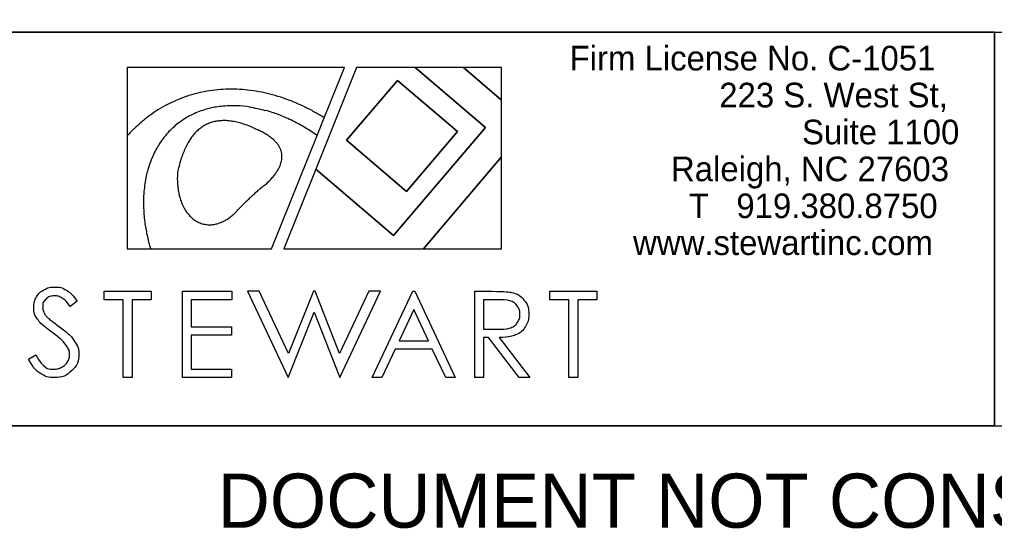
# Model space of a CAD drawing. Extents: x 1637092 to 1638792, y 884647 to 885778.
# Drawn here: x 1638567.6 to 1638666.6, y 885534.2 to 885585.9 of the extents above; entities that cross this region are included whole.
import ezdxf

# ---------------------------------------------------------------- set-up
doc = ezdxf.new("R2010")
doc.units = 0
for name, color, linetype in [('Default', 7, 'Continuous'), ('Sheet Plan And Profile CELL', 7, 'Continuous'), ('Sheet Profile CELL', 7, 'Continuous')]:
    doc.layers.add(name, color=color, linetype=linetype)

msp = doc.modelspace()

# ---------------------------------------------------------------- linework, layer by layer
at = {"layer": 'Default'}
for p, q in [((1638600.578, 885580.988), (1638578.504, 885580.988)), ((1638578.504, 885580.988), (1638578.504, 885574.036)), ((1638601.809, 885580.988), (1638597.661, 885570.674)), ((1638598.525, 885575.881), (1638600.578, 885580.988)), ((1638607.761, 885580.988), (1638601.809, 885580.988)), ((1638607.761, 885580.988), (1638614.913, 885574.896)), ((1638612.655, 885580.988), (1638607.761, 885580.988)), ((1638614.913, 885574.896), (1638607.761, 885580.988)), ((1638616.541, 885580.988), (1638612.655, 885580.988)), ((1638612.655, 885580.988), (1638616.541, 885577.678)), ((1638616.541, 885577.678), (1638612.655, 885580.988)), ((1638616.541, 885577.678), (1638616.541, 885580.988)), ((1638591.027, 885578.66), (1638591.035, 885578.66)), ((1638583.451, 885577.647), (1638583.425, 885577.618)), ((1638584.516, 885578.05), (1638584.472, 885578.037)), ((1638616.541, 885571.913), (1638616.541, 885577.678)), ((1638590.939, 885576.954), (1638590.98, 885576.976)), ((1638596.511, 885577), (1638596.517, 885576.997)), ((1638597.796, 885574.069), (1638598.525, 885575.881)), ((1638614.913, 885574.896), (1638605.574, 885563.933)), ((1638605.574, 885563.933), (1638614.913, 885574.896)), ((1638578.504, 885574.036), (1638578.504, 885562.584)), ((1638593.178, 885562.584), (1638597.796, 885574.069)), ((1638606.895, 885568.393), (1638612.078, 885574.479)), ((1638616.541, 885571.913), (1638608.594, 885562.584)), ((1638608.594, 885562.584), (1638616.541, 885571.913)), ((1638616.541, 885562.584), (1638616.541, 885571.913)), ((1638597.661, 885570.674), (1638594.408, 885562.584)), ((1638605.574, 885563.933), (1638597.661, 885570.674)), ((1638597.661, 885570.674), (1638605.574, 885563.933)), ((1638578.504, 885562.584), (1638580.879, 885562.584)), ((1638580.879, 885562.584), (1638593.178, 885562.584)), ((1638594.408, 885562.584), (1638608.594, 885562.584)), ((1638608.594, 885562.584), (1638616.541, 885562.584)), ((1638591.918, 885558.256), (1638590.726, 885558.256)), ((1638590.726, 885558.256), (1638594.843, 885549.506)), ((1638594.895, 885551.95), (1638591.918, 885558.256)), ((1638597.418, 885558.256), (1638594.895, 885551.95)), ((1638597.589, 885558.256), (1638597.418, 885558.256)), ((1638600.067, 885551.95), (1638597.589, 885558.256)), ((1638603.044, 885558.256), (1638600.067, 885551.95)), ((1638600.106, 885549.506), (1638604.236, 885558.256)), ((1638604.236, 885558.256), (1638603.044, 885558.256)), ((1638594.843, 885549.506), (1638597.502, 885556.13)), ((1638597.502, 885556.13), (1638600.106, 885549.506)), ((1638566.618, 885544.59), (1638766.656, 885544.59)), ((1638566.618, 885544.59), (1638766.656, 885544.59))]:
    msp.add_line(p, q, dxfattribs=at)
for points in [[(1638566.606, 885584.59), (1638666.606, 885584.59), (1638666.606, 885544.59), (1638566.606, 885544.59)], [(1638666.606, 885584.59), (1638566.606, 885584.59), (1638566.606, 885544.59), (1638666.606, 885544.59)]]:
    msp.add_lwpolyline(points, close=True, dxfattribs=at)
for points in [[(1638600.783, 885573.599), (1638605.967, 885579.684), (1638612.078, 885574.479), (1638606.895, 885568.393), (1638600.783, 885573.599)], [(1638612.078, 885574.479), (1638605.967, 885579.684), (1638600.783, 885573.599), (1638606.895, 885568.393)], [(1638582.491, 885577.175), (1638582.568, 885577.219)], [(1638592.612, 885576.621), (1638592.568, 885576.6)], [(1638579.21, 885574.761), (1638579.15, 885574.719)], [(1638592.177, 885568.811), (1638592.056, 885568.711)], [(1638592.359, 885568.954), (1638592.278, 885568.893)], [(1638592.489, 885569.033), (1638592.419, 885568.996)], [(1638589.978, 885566.767), (1638589.877, 885566.665)], [(1638576.161, 885557.398), (1638576.161, 885558.256), (1638580.951, 885558.256), (1638580.951, 885557.398), (1638579.002, 885557.398), (1638579.002, 885549.506), (1638578.11, 885549.506), (1638578.11, 885557.398), (1638576.161, 885557.398)], [(1638584.118, 885558.256), (1638589.134, 885558.256), (1638589.134, 885557.398), (1638584.989, 885557.398), (1638584.989, 885554.656), (1638589.098, 885554.656), (1638589.098, 885553.799), (1638584.989, 885553.799), (1638584.989, 885550.363), (1638589.098, 885550.363), (1638589.098, 885549.506), (1638584.118, 885549.506), (1638584.118, 885558.256)], [(1638607.739, 885558.256), (1638611.82, 885549.506), (1638610.874, 885549.506), (1638609.501, 885552.389), (1638605.732, 885552.389), (1638604.371, 885549.506), (1638603.396, 885549.506), (1638607.526, 885558.256), (1638607.739, 885558.256)], [(1638613.834, 885558.256), (1638615.573, 885558.256)], [(1638616.28, 885553.565), (1638619.424, 885549.506), (1638618.342, 885549.506), (1638615.198, 885553.565), (1638614.705, 885553.565), (1638614.705, 885549.506), (1638613.834, 885549.506), (1638613.834, 885558.256)], [(1638621.43, 885557.398), (1638621.43, 885558.256), (1638626.219, 885558.256), (1638626.219, 885557.398), (1638624.271, 885557.398), (1638624.271, 885549.506), (1638623.378, 885549.506), (1638623.378, 885557.398), (1638621.43, 885557.398)], [(1638573.437, 885557.259), (1638572.724, 885556.718)], [(1638614.705, 885557.398), (1638614.705, 885554.423), (1638616.212, 885554.411)], [(1638616.247, 885557.398), (1638614.705, 885557.398)], [(1638607.627, 885556.402), (1638606.13, 885553.232), (1638609.12, 885553.232), (1638607.627, 885556.402)], [(1638568.471, 885551.355), (1638569.214, 885551.801)]]:
    msp.add_lwpolyline(points, dxfattribs=at)
for centre, radius, start, end in [((1638589.027, 885564.484), 14.3, 95.33896, 99.74382), ((1638589.027, 885564.484), 14.3, 95.33896, 99.74382), ((1638589.052, 885564.219), 14.566, 91.0141, 95.33896), ((1638589.052, 885564.219), 14.566, 91.0141, 95.33896), ((1638589.068, 885563.338), 15.448, 86.81452, 91.0141), ((1638589.068, 885563.338), 15.448, 86.81452, 91.0141), ((1638589.068, 885563.338), 15.448, 82.68224, 86.81452), ((1638589.068, 885563.338), 15.448, 82.68224, 86.81452), ((1638588.87, 885561.866), 16.932, 78.75005, 82.68224), ((1638588.87, 885561.866), 16.932, 78.75005, 82.68224), ((1638588.995, 885564.67), 14.111, 108.6948, 113.13309), ((1638588.995, 885564.67), 14.111, 108.6948, 113.13309), ((1638588.852, 885565.237), 13.527, 104.17801, 108.6948), ((1638588.852, 885565.237), 13.527, 104.17801, 108.6948), ((1638588.995, 885564.67), 14.111, 99.74382, 104.17801), ((1638588.995, 885564.67), 14.111, 99.74382, 104.17801), ((1638588.985, 885562.441), 16.346, 74.86342, 78.75005), ((1638588.985, 885562.441), 16.346, 74.86342, 78.75005), ((1638588.375, 885560.187), 18.681, 71.22794, 74.86342), ((1638588.375, 885560.187), 18.681, 71.22794, 74.86342), ((1638588.748, 885561.284), 17.523, 67.61084, 71.22794), ((1638588.748, 885561.284), 17.523, 67.61084, 71.22794), ((1638588.574, 885565.564), 13.108, 121.98098, 126.38314), ((1638588.574, 885565.564), 13.108, 121.98098, 126.38314), ((1638589.192, 885564.574), 14.274, 117.64902, 121.98098), ((1638589.192, 885564.574), 14.274, 117.64902, 121.98098), ((1638588.574, 885565.564), 13.108, 113.13309, 117.64902), ((1638588.574, 885565.564), 13.108, 113.13309, 117.64902), ((1638589.095, 885567.884), 9.226, 104.98979, 114.2575), ((1638589.095, 885567.884), 9.226, 104.98979, 114.2575), ((1638588.947, 885568.437), 8.654, 95.97029, 104.98979), ((1638588.947, 885568.437), 8.654, 95.97029, 104.98979), ((1638589.29, 885565.152), 11.957, 88.29908, 95.97029), ((1638589.29, 885565.152), 11.957, 88.29908, 95.97029), ((1638589.342, 885566.901), 10.207, 80.76366, 88.29908), ((1638589.342, 885566.901), 10.207, 80.76366, 88.29908), ((1638588.404, 885561.371), 15.789, 74.71033, 80.76366), ((1638588.404, 885561.371), 15.789, 74.71033, 80.76366), ((1638587.577, 885558.441), 20.597, 64.27468, 67.61084), ((1638587.577, 885558.441), 20.597, 64.27468, 67.61084), ((1638587.931, 885559.192), 19.767, 60.92836, 64.27468), ((1638587.931, 885559.192), 19.767, 60.92836, 64.27468), ((1638589.635, 885564.124), 14.897, 126.38314, 130.51246), ((1638589.635, 885564.124), 14.897, 126.38314, 130.51246), ((1638588.617, 885568.944), 8.064, 114.2575, 124.17212), ((1638588.617, 885568.944), 8.064, 114.2575, 124.17212), ((1638589.396, 885564.86), 12.193, 68.58238, 74.71033), ((1638589.396, 885564.86), 12.193, 68.58238, 74.71033), ((1638586.548, 885557.598), 19.993, 63.79776, 68.58238), ((1638586.548, 885557.598), 19.993, 63.79776, 68.58238), ((1638587.931, 885559.192), 19.767, 57.5922, 60.92836), ((1638587.931, 885559.192), 19.767, 57.5922, 60.92836), ((1638589.192, 885564.574), 14.274, 134.70691, 138.48502), ((1638589.192, 885564.574), 14.274, 134.70691, 138.48502), ((1638588.976, 885564.896), 13.881, 130.51246, 134.70691), ((1638588.976, 885564.896), 13.881, 130.51246, 134.70691), ((1638589.156, 885568.409), 8.821, 134.18211, 143.7045), ((1638589.156, 885568.409), 8.821, 134.18211, 143.7045), ((1638588.573, 885569.009), 7.985, 124.17212, 134.18211), ((1638588.573, 885569.009), 7.985, 124.17212, 134.18211), ((1638588.418, 885571.561), 4.097, 126.10024, 132.84964), ((1638588.418, 885571.561), 4.097, 126.10024, 132.84964), ((1638588.202, 885571.858), 3.73, 119.02596, 126.10024), ((1638588.202, 885571.858), 3.73, 119.02596, 126.10024), ((1638588.17, 885571.915), 3.664, 111.82778, 119.02597), ((1638588.17, 885571.915), 3.664, 111.82778, 119.02597), ((1638588.208, 885571.82), 3.767, 104.72849, 111.82778), ((1638588.208, 885571.82), 3.767, 104.72849, 111.82778), ((1638588.242, 885571.69), 3.901, 97.90175, 104.7285), ((1638588.242, 885571.69), 3.901, 97.90175, 104.7285), ((1638588.323, 885571.105), 4.492, 91.53976, 97.90175), ((1638588.323, 885571.105), 4.492, 91.53976, 97.90175), ((1638588.333, 885570.759), 4.838, 85.68251, 91.53976), ((1638588.333, 885570.759), 4.838, 85.68251, 91.53976), ((1638588.245, 885569.592), 6.008, 80.42702, 85.68251), ((1638588.245, 885569.592), 6.008, 80.42702, 85.68251), ((1638588.148, 885569.021), 6.587, 75.69708, 80.42702), ((1638588.148, 885569.021), 6.587, 75.69708, 80.42702), ((1638587.68, 885567.184), 8.483, 71.52919, 75.69708), ((1638587.68, 885567.184), 8.483, 71.52919, 75.69708), ((1638587.036, 885565.256), 10.516, 67.79994, 71.52919), ((1638587.036, 885565.256), 10.516, 67.79994, 71.52919), ((1638587.828, 885567.197), 8.419, 63.63204, 67.79994), ((1638587.828, 885567.197), 8.419, 63.63204, 67.79994), ((1638589.073, 885568.63), 6.6, 63.90222, 67.78989), ((1638589.073, 885568.63), 6.6, 63.90222, 67.78989), ((1638588.404, 885561.371), 15.789, 58.77838, 63.79776), ((1638588.404, 885561.371), 15.789, 58.77838, 63.79776), ((1638587.582, 885560.014), 17.375, 53.99375, 58.77838), ((1638587.582, 885560.014), 17.375, 53.99375, 58.77838), ((1638589.695, 885570.484), 5.772, 144.89501, 150.09139), ((1638589.695, 885570.484), 5.772, 144.89501, 150.09139), ((1638589.284, 885570.773), 5.269, 139.15431, 144.89501), ((1638589.284, 885570.773), 5.269, 139.15431, 144.89501), ((1638588.603, 885571.361), 4.37, 132.84964, 139.15431), ((1638588.603, 885571.361), 4.37, 132.84964, 139.15431), ((1638588.165, 885566.777), 8.663, 60.50912, 63.90221), ((1638588.165, 885566.777), 8.663, 60.50912, 63.90221), ((1638589.149, 885568.517), 6.664, 56.62145, 60.50912), ((1638589.149, 885568.517), 6.664, 56.62145, 60.50912), ((1638590.133, 885570.011), 4.875, 52.07574, 56.62144), ((1638590.133, 885570.011), 4.875, 52.07574, 56.62144), ((1638590.492, 885570.471), 4.292, 46.84444, 52.07574), ((1638590.492, 885570.471), 4.292, 46.84444, 52.07574), ((1638588.62, 885568.803), 8.157, 143.7045, 153.10241), ((1638588.62, 885568.803), 8.157, 143.7045, 153.10241), ((1638591.73, 885569.383), 8.087, 154.70217, 158.82578), ((1638591.73, 885569.383), 8.087, 154.70217, 158.82578), ((1638591.046, 885569.707), 7.331, 150.09139, 154.70217), ((1638591.046, 885569.707), 7.331, 150.09139, 154.70217), ((1638591.245, 885571.275), 3.191, 40.77679, 46.84444), ((1638591.245, 885571.275), 3.191, 40.77679, 46.84444), ((1638591.514, 885571.507), 2.835, 33.89614, 40.77679), ((1638591.514, 885571.507), 2.835, 33.89614, 40.77679), ((1638591.991, 885571.827), 2.26, 26.18824, 33.89614), ((1638591.991, 885571.827), 2.26, 26.18824, 33.89614), ((1638592.137, 885571.899), 2.098, 17.85938, 26.18823), ((1638592.137, 885571.899), 2.098, 17.85938, 26.18823), ((1638591.214, 885567.487), 11.065, 153.10241, 161.16886), ((1638591.214, 885567.487), 11.065, 153.10241, 161.16886), ((1638593.949, 885568.524), 10.467, 158.82578, 162.45014), ((1638593.949, 885568.524), 10.467, 158.82578, 162.45014), ((1638592.298, 885571.951), 1.928, 9.17109, 17.85938), ((1638592.298, 885571.951), 1.928, 9.17109, 17.85938), ((1638592.293, 885571.95), 1.934, 0.50696, 9.17108), ((1638592.293, 885571.95), 1.934, 0.50696, 9.17108), ((1638592.101, 885571.948), 2.126, 352.24438, 0.50695), ((1638592.101, 885571.948), 2.126, 352.24438, 0.50695), ((1638589.642, 885568.023), 9.405, 161.16886, 169.12791), ((1638589.642, 885568.023), 9.405, 161.16886, 169.12791), ((1638593.823, 885568.411), 10.376, 165.69373, 169.31809), ((1638593.823, 885568.411), 10.376, 165.69373, 169.31809), ((1638596.321, 885567.774), 12.955, 162.45014, 165.69373), ((1638596.321, 885567.774), 12.955, 162.45014, 165.69373), ((1638590, 885572.808), 4.412, 326.75387, 331.89068), ((1638590, 885572.808), 4.412, 326.75387, 331.89068), ((1638591.004, 885572.271), 3.274, 331.89068, 337.85452), ((1638591.004, 885572.271), 3.274, 331.89068, 337.85452), ((1638591.346, 885572.132), 2.904, 337.85452, 344.63043), ((1638591.346, 885572.132), 2.904, 337.85452, 344.63043), ((1638591.928, 885571.972), 2.3, 344.63043, 352.24439), ((1638591.928, 885571.972), 2.3, 344.63043, 352.24439), ((1638594.693, 885567.053), 14.548, 169.1279, 175.52553), ((1638594.693, 885567.053), 14.548, 169.1279, 175.52553), ((1638590.378, 885569.68), 6.781, 179.11246, 183.50718), ((1638590.378, 885569.68), 6.781, 179.11246, 183.50718), ((1638591.186, 885569.667), 7.589, 174.9583, 179.11247), ((1638591.186, 885569.667), 7.589, 174.9583, 179.11247), ((1638586.513, 885575.616), 8.894, 315.14136, 318.47442), ((1638586.513, 885575.616), 8.894, 315.14136, 318.47442), ((1638588.044, 885574.26), 6.849, 318.47442, 322.29152), ((1638588.044, 885574.26), 6.849, 318.47442, 322.29152), ((1638589.497, 885573.137), 5.012, 322.29152, 326.75387), ((1638589.497, 885573.137), 5.012, 322.29152, 326.75387), ((1638592.344, 885569.8), 8.75, 183.50718, 187.66135), ((1638592.344, 885569.8), 8.75, 183.50718, 187.66135), ((1638598.202, 885561.436), 9.524, 129.24937, 130.18873), ((1638596.359, 885563.692), 6.611, 128.12185, 129.24938), ((1638596.359, 885563.692), 6.611, 128.12185, 129.24938), ((1638594.219, 885566.419), 3.145, 126.27417, 128.12186), ((1638593.331, 885567.629), 1.643, 123.71796, 126.27414), ((1638593.331, 885567.629), 1.643, 123.71796, 126.27414), ((1638592.557, 885568.788), 0.249, 118.06073, 123.718), ((1638593.014, 885567.931), 1.221, 115.50456, 118.0608), ((1638588.01, 885574.126), 6.782, 311.32427, 315.14136), ((1638588.01, 885574.126), 6.782, 311.32427, 315.14136), ((1638591.403, 885567.31), 11.248, 175.52553, 181.98726), ((1638591.403, 885567.31), 11.248, 175.52553, 181.98726), ((1638589.013, 885569.352), 5.389, 187.66135, 192.95549), ((1638589.013, 885569.352), 5.389, 187.66135, 192.95549), ((1638590.574, 885569.711), 6.991, 192.95549, 198.18402), ((1638590.574, 885569.711), 6.991, 192.95549, 198.18402), ((1638617.92, 885539.064), 39.348, 133.16627, 133.53679), ((1638617.92, 885539.064), 39.348, 133.16627, 133.53679), ((1638620.687, 885536.113), 43.393, 132.79754, 133.16627), ((1638620.687, 885536.113), 43.393, 132.79754, 133.16627), ((1638615.859, 885541.328), 36.286, 132.39431, 132.79754), ((1638615.859, 885541.328), 36.286, 132.39431, 132.79754), ((1638613.675, 885543.72), 33.047, 131.95155, 132.39431), ((1638613.675, 885543.72), 33.047, 131.95155, 132.39431), ((1638609.744, 885548.094), 27.166, 131.46321, 131.95154), ((1638609.744, 885548.094), 27.166, 131.46321, 131.95154), ((1638605.136, 885553.308), 20.208, 130.86507, 131.46321), ((1638605.136, 885553.308), 20.208, 130.86507, 131.46321), ((1638602.256, 885556.638), 15.805, 130.18873, 130.86507), ((1638602.256, 885556.638), 15.805, 130.18873, 130.86507), ((1638598.746, 885567.565), 18.595, 181.98726, 187.01165), ((1638598.746, 885567.565), 18.595, 181.98726, 187.01165), ((1638588.163, 885568.919), 4.454, 198.18403, 204.73613), ((1638588.163, 885568.919), 4.454, 198.18403, 204.73613), ((1638588.785, 885569.205), 5.138, 204.73614, 211.51028), ((1638588.785, 885569.205), 5.138, 204.73614, 211.51028), ((1638602.406, 885554.499), 17.464, 135.36978, 135.84187), ((1638613.198, 885543.845), 32.628, 134.99547, 135.36979), ((1638613.198, 885543.845), 32.628, 134.99547, 135.36979), ((1638609.874, 885547.169), 27.928, 134.59089, 134.99547), ((1638609.874, 885547.169), 27.928, 134.59089, 134.99547), ((1638619.999, 885536.9), 42.349, 134.24875, 134.59089), ((1638619.999, 885536.9), 42.349, 134.24875, 134.59089), ((1638615.397, 885541.623), 35.754, 133.87638, 134.24875), ((1638615.397, 885541.623), 35.754, 133.87638, 134.24875), ((1638623.079, 885533.634), 46.838, 133.53679, 133.87639), ((1638623.079, 885533.634), 46.838, 133.53679, 133.87639), ((1638587.413, 885568.365), 3.529, 211.51028, 219.6861), ((1638587.413, 885568.365), 3.529, 211.51028, 219.6861), ((1638587.484, 885568.423), 3.621, 219.6861, 228.4088), ((1638587.484, 885568.423), 3.621, 219.6861, 228.4088), ((1638585.589, 885570.281), 5.615, 302.72034, 308.32572), ((1638585.589, 885570.281), 5.615, 302.72034, 308.32572), ((1638586.167, 885569.55), 4.684, 308.32572, 314.05681), ((1638586.167, 885569.55), 4.684, 308.32572, 314.05681), ((1638586.02, 885569.703), 4.896, 314.05681, 319.66219), ((1638586.02, 885569.703), 4.896, 314.05681, 319.66219), ((1638609.806, 885547.313), 27.779, 135.84186, 136.21617), ((1638609.806, 885547.313), 27.779, 135.84186, 136.21617), ((1638595.035, 885567.109), 14.856, 187.01165, 192.25448), ((1638595.035, 885567.109), 14.856, 187.01165, 192.25448), ((1638586.995, 885567.873), 2.885, 228.4088, 238.184), ((1638586.995, 885567.873), 2.885, 228.4088, 238.184), ((1638586.903, 885567.724), 2.71, 238.184, 248.56848), ((1638586.903, 885567.724), 2.71, 238.184, 248.56848), ((1638586.909, 885567.741), 2.728, 248.56848, 258.91877), ((1638586.909, 885567.741), 2.728, 248.56848, 258.91877), ((1638586.852, 885567.449), 2.431, 258.91877, 269.50929), ((1638586.852, 885567.449), 2.431, 258.91877, 269.50929), ((1638586.858, 885568.179), 3.161, 269.50929, 278.79296), ((1638586.858, 885568.179), 3.161, 269.50929, 278.79296), ((1638586.933, 885567.695), 2.671, 278.79296, 288.01029), ((1638586.933, 885567.695), 2.671, 278.79296, 288.01029), ((1638586.468, 885569.127), 4.176, 288.01029, 295.379), ((1638586.468, 885569.127), 4.176, 288.01029, 295.379), ((1638586.854, 885568.313), 3.276, 295.379, 302.72034), ((1638586.854, 885568.313), 3.276, 295.379, 302.72034), ((1638596.324, 885567.389), 16.175, 192.25448, 197.27887), ((1638596.324, 885567.389), 16.175, 192.25448, 197.27887)]:
    msp.add_arc(centre, radius, start, end, dxfattribs=at)
for points in [[(1638569.214, 885551.801), (1638569.999, 885550.356), (1638571.027, 885550.356), (1638571.467, 885550.356), (1638571.853, 885550.561), (1638572.24, 885550.766), (1638572.442, 885551.111), (1638572.644, 885551.456), (1638572.644, 885551.842), (1638572.644, 885552.282), (1638572.347, 885552.704), (1638571.936, 885553.287), (1638570.848, 885554.107), (1638569.755, 885554.934), (1638569.487, 885555.303), (1638569.023, 885555.922), (1638569.023, 885556.642), (1638569.023, 885557.213), (1638569.297, 885557.683), (1638569.57, 885558.153), (1638570.066, 885558.424), (1638570.562, 885558.695), (1638571.144, 885558.695), (1638571.762, 885558.695), (1638572.3, 885558.388), (1638572.837, 885558.081), (1638573.437, 885557.259)], [(1638615.573, 885558.256), (1638617.028, 885558.256), (1638617.545, 885558.136), (1638618.323, 885557.957), (1638618.809, 885557.37), (1638619.296, 885556.783), (1638619.296, 885555.925), (1638619.296, 885555.21), (1638618.961, 885554.668), (1638618.625, 885554.125), (1638618.002, 885553.848), (1638617.378, 885553.571), (1638616.28, 885553.565)], [(1638572.724, 885556.718), (1638572.23, 885557.372), (1638571.882, 885557.58), (1638571.535, 885557.788), (1638571.124, 885557.788), (1638570.595, 885557.788), (1638570.259, 885557.467), (1638569.923, 885557.146), (1638569.923, 885556.676), (1638569.923, 885556.391), (1638570.042, 885556.123), (1638570.161, 885555.856), (1638570.476, 885555.54), (1638570.649, 885555.374), (1638571.606, 885554.666), (1638572.742, 885553.828), (1638573.164, 885553.174), (1638573.586, 885552.52), (1638573.586, 885551.86), (1638573.586, 885550.909), (1638572.864, 885550.207), (1638572.142, 885549.506), (1638571.109, 885549.506), (1638570.313, 885549.506), (1638569.665, 885549.931), (1638569.017, 885550.356), (1638568.471, 885551.355)], [(1638616.212, 885554.411), (1638617.087, 885554.411), (1638617.506, 885554.577), (1638617.926, 885554.744), (1638618.161, 885555.11), (1638618.397, 885555.476), (1638618.397, 885555.928), (1638618.397, 885556.369), (1638618.158, 885556.729), (1638617.92, 885557.089), (1638617.533, 885557.243), (1638617.146, 885557.398), (1638616.247, 885557.398)]]:
    msp.add_open_spline(points, degree=3, dxfattribs=at)
at = {"layer": 'Sheet Plan And Profile CELL'}
msp.add_line((1638566.618, 885544.59), (1638766.656, 885544.59), dxfattribs=at)
at = {"layer": 'Sheet Profile CELL'}
msp.add_lwpolyline([(1638566.606, 885697.09), (1638566.606, 885584.59), (1638766.656, 885584.59)], dxfattribs=at)

# ---------------------------------------------------------------- texts
at = {"layer": 'Default'}
for s, height, rotation, p in [('Firm License No. C-1051', 2.5, 0, (1638623.45, 885580.692)), ('223 S. West St,', 2.5, 0, (1638638.656, 885576.942)), ('Suite 1100', 2.5, 0, (1638647.062, 885573.192)), ('Raleigh, NC 27603', 2.5, 0, (1638633.75, 885569.442)), ('T   919.380.8750', 2.5, 0, (1638635.562, 885565.692)), ('www.stewartinc.com', 2.5, 0, (1638629.901, 885561.942)), ('DOCUMENT NOT CONSIDERED FINAL', 5.5, 360, (1638587.689, 885534.245)), ('DOCUMENT NOT CONSIDERED FINAL', 5.5, 360, (1638587.689, 885534.245))]:
    msp.add_text(s, height=height, rotation=rotation, dxfattribs=at).set_placement(p)

doc.saveas('drawing.dxf')
